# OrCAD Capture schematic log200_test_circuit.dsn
size A; title: LOG200 Precision, High-Speed Logarithmic Amplifier; rev: 1.0; company: Texas Instruments Inc.; note: Datasheet: SBOSA28   EVM: SBOU301   Aug-'23
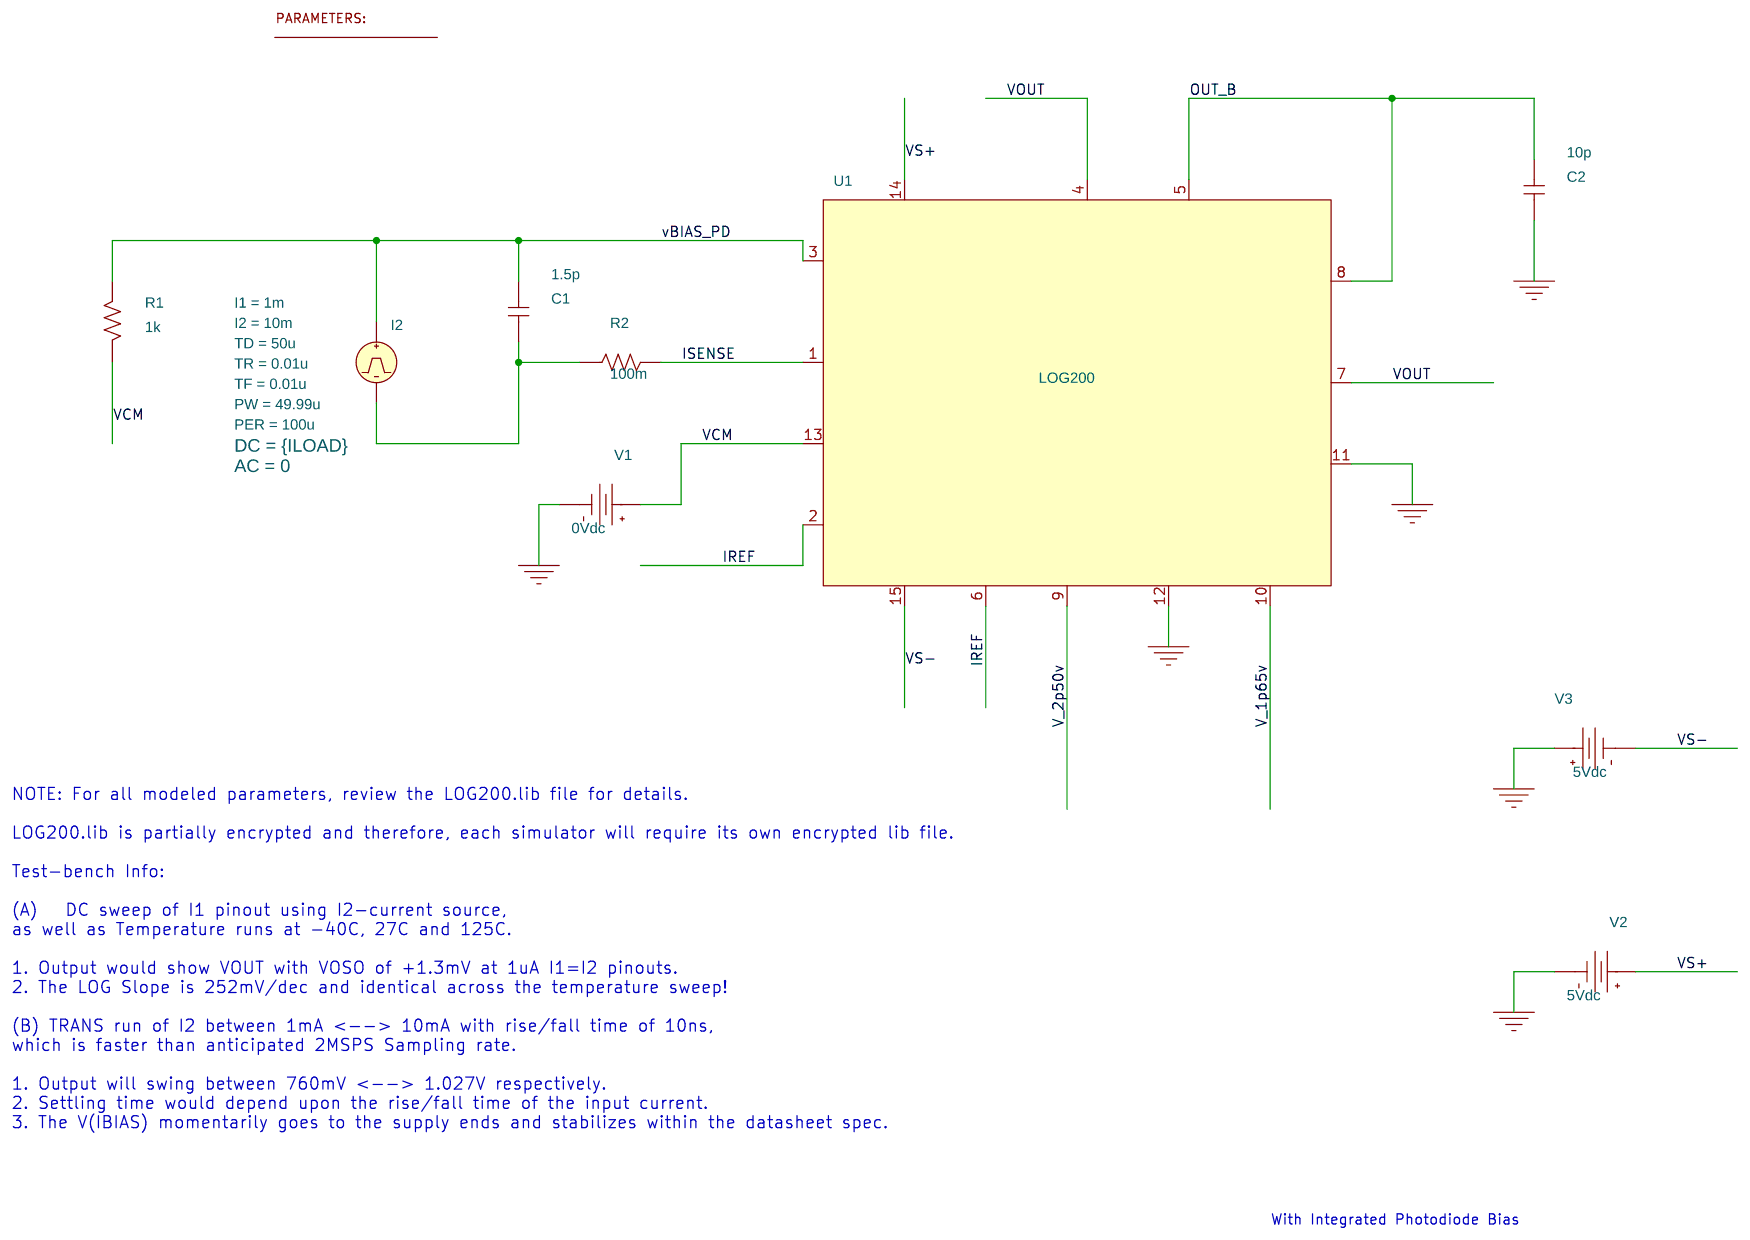
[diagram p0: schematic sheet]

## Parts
1  PARAM
C1  1.5p  [cap196]
C2  10p  [cap196]
I2  IPULSE
R1  1k  [AXRC05]
R2  100m  [AXRC05]
U1  LOG200
V1  VDC
V2  VDC
V3  VDC

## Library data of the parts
1 = PARAM: ILOAD: 1u
C1 C2 = C
I2 = IPULSE: AC: 0; AppProp: Pulse$Current$1$-1; DC: {ILOAD}; I1: 1m; I2: 10m; PER: 100u; PW: 49.99u; TD: 50u; TF: 0.01u; TR: 0.01u
R1 R2 = R
U1 = LOG200
V1 = VDC: DC: 0Vdc
V2 V3 = VDC: DC: 5Vdc

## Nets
0: C2.2 U1.11(REFA) U1.12(REFGND) V1.1(-) V2.1(-) V3.0(+)
IREF: U1.2(I2) U1.6(IREF)
ISENSE: R2.2 U1.1(I1)
OUT_B: C2.1 U1.5(IN-) U1.8(OUTB)
V_1p65v: U1.10(REF165)
V_2p50v: U1.9(REF25)
vBIAS_PD: C1.1 I2.1(+) R1.2 U1.3(IBIAS)
VCM: R1.1 U1.13(VCM) V1.0(+)
VOUT: U1.4(IN+) U1.7(OUTA)
VS+: U1.14(VS+) V2.0(+)
VS-: U1.15(VS-) V3.1(-)
N92039: C1.2 I2.2(-) R2.1

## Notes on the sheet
- NOTE: For all modeled parameters, review the LOG200.lib file for details.
  LOG200.lib is partially encrypted and therefore, each simulator will require its own encrypted lib file.
  Test-bench Info:
  (A)   DC sweep of I1 pinout using I2-current source,
  as well as Temperature runs at -40C, 27C and 125C.
  1. Output would show VOUT with VOSO of +1.3mV at 1uA I1=I2 pinouts.
  2. The LOG Slope is 252mV/dec and identical across the temperature sweep!
  (B) TRANS run of I2 between 1mA <--> 10mA with rise/fall time of 10ns,
  which is faster than anticipated 2MSPS Sampling rate.
  1. Output will swing between 760mV <--> 1.027V respectively.
  2. Settling time would depend upon the rise/fall time of the input current.
  3. The V(IBIAS) momentarily goes to the supply ends and stabilizes within the datasheet spec.
- With Integrated Photodiode Bias
